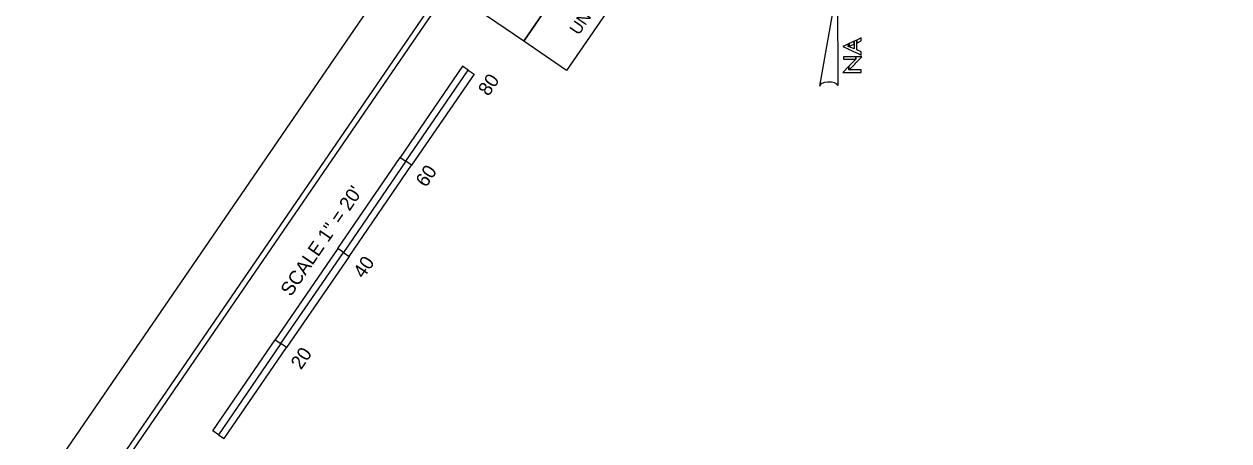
# Model space of a CAD drawing. Extents: x 1439200 to 1642184, y 394112 to 606444.
# Drawn here: x 1641658.3 to 1641876.4, y 394691.9 to 394767.3 of the extents above; entities that cross this region are included whole.
import ezdxf

# ---------------------------------------------------------------- set-up
doc = ezdxf.new("R2010")
doc.units = 0
for name, color, linetype in [('North Arrow NAD83 CELL', 7, 'Continuous'), ('Old_Level_20', 7, 'Continuous'), ('Old_Level_60', 7, 'Continuous'), ('Sheet Plot Border Inside CELL', 7, 'Continuous'), ('Sheet Plot Border Outside CELL', 7, 'Continuous'), ('Sheet Sticker Exception Certification CELL', 7, 'Continuous'), ('UC Plan Sheet 34 CELL', 7, 'Continuous')]:
    doc.layers.add(name, color=color, linetype=linetype)

msp = doc.modelspace()

# ---------------------------------------------------------------- linework, layer by layer
at = {"layer": 'North Arrow NAD83 CELL'}
for p, q in [((1641805.65, 394775), (1641802.31, 394756.1)), ((1641805.67, 394756.18), (1641805.65, 394775))]:
    msp.add_line(p, q, dxfattribs=at)
for points in [[(1641809.04, 394762.09), (1641809.86, 394761.71), (1641809.86, 394762.26), (1641809.04, 394762.62), (1641809.04, 394764.41), (1641808.61, 394764.21), (1641808.61, 394762.82), (1641807.89, 394763.14), (1641807.88, 394763.14), (1641807.7, 394763.21), (1641807.7, 394763.21), (1641807.52, 394763.26), (1641807.52, 394763.7), (1641806.56, 394763.25), (1641807.52, 394762.8), (1641807.7, 394762.72), (1641807.7, 394762.72), (1641807.88, 394762.63), (1641807.89, 394762.63), (1641808.61, 394762.29)], [(1641807.52, 394763.26), (1641807.7, 394763.31), (1641807.7, 394763.78), (1641807.52, 394763.7)], [(1641807.89, 394763.38), (1641808.61, 394763.7), (1641808.61, 394764.21), (1641807.89, 394763.87), (1641807.88, 394763.87), (1641807.7, 394763.79), (1641807.7, 394763.78), (1641807.7, 394763.31), (1641807.7, 394763.31), (1641807.88, 394763.38)], [(1641809.04, 394763.88), (1641809.86, 394764.25), (1641809.86, 394764.79), (1641809.04, 394764.41)], [(1641808.89, 394758.57), (1641809.87, 394758.57), (1641809.87, 394759.04), (1641808.89, 394759.04), (1641808.68, 394759.04), (1641808.5, 394759.04), (1641808.01, 394759.04), (1641807.82, 394759.04), (1641807.65, 394759.04), (1641807.65, 394759.71), (1641806.56, 394758.57), (1641807.65, 394758.57), (1641807.82, 394758.57), (1641808.01, 394758.57), (1641808.5, 394758.57), (1641808.68, 394758.57)], [(1641808.68, 394760.94), (1641808.89, 394760.94), (1641808.89, 394761.41), (1641808.68, 394761.41), (1641808.5, 394761.41), (1641808.01, 394761.41), (1641807.82, 394761.41), (1641806.68, 394761.41), (1641806.68, 394760.94), (1641807.82, 394760.94), (1641808.01, 394760.94), (1641808.5, 394760.94)], [(1641809.86, 394761.29), (1641809.99, 394761.41), (1641809.86, 394761.41), (1641808.89, 394761.41), (1641808.89, 394760.94), (1641808.68, 394760.76), (1641808.5, 394760.59), (1641808.01, 394760.07), (1641807.82, 394759.88), (1641807.65, 394759.71), (1641807.65, 394759.04), (1641807.82, 394759.17), (1641808.01, 394759.35), (1641808.5, 394759.87), (1641808.68, 394760.05), (1641808.89, 394760.27)]]:
    msp.add_lwpolyline(points, close=True, dxfattribs=at)
msp.add_ellipse((1641804, 394756.03), major_axis=(1.69, -0.01), ratio=0.461098, start_param=0.201328, end_param=3.141593, dxfattribs=at)
at = {"layer": 'Old_Level_20'}
for points in [[(1641727.43, 394742.48), (1641738.74, 394758.97), (1641737.71, 394759.68), (1641726.4, 394743.18), (1641727.43, 394742.48)], [(1641717.15, 394725.27), (1641728.46, 394741.77), (1641727.43, 394742.48), (1641716.12, 394725.98), (1641717.15, 394725.27)], [(1641704.81, 394709.49), (1641716.12, 394725.98), (1641715.09, 394726.69), (1641703.78, 394710.19), (1641704.81, 394709.49)], [(1641694.53, 394692.29), (1641705.84, 394708.78), (1641704.81, 394709.49), (1641693.5, 394692.99), (1641694.53, 394692.29)]]:
    msp.add_lwpolyline(points, dxfattribs=at)
for points in [[(1641727.43, 394742.48), (1641738.74, 394758.97), (1641739.78, 394758.26), (1641728.46, 394741.77)], [(1641715.09, 394726.69), (1641726.4, 394743.18), (1641727.43, 394742.48), (1641716.12, 394725.98)], [(1641704.81, 394709.49), (1641716.12, 394725.98), (1641717.15, 394725.27), (1641705.84, 394708.78)], [(1641692.47, 394693.7), (1641703.78, 394710.19), (1641704.81, 394709.49), (1641693.5, 394692.99)]]:
    msp.add_lwpolyline(points, close=True, dxfattribs=at)
at = {"layer": 'Old_Level_60'}
msp.add_lwpolyline([(1641735.12, 394773.58), (1641780.37, 394839.57), (1641794.03, 394830.21), (1641748.77, 394764.22)], close=True, dxfattribs=at)
at = {"layer": 'Sheet Plot Border Inside CELL'}
msp.add_lwpolyline([(1641827.57, 394910.19), (1641450.57, 394360.44), (1641798.64, 394121.75), (1642175.63, 394671.51)], close=True, dxfattribs=at)
at = {"layer": 'Sheet Plot Border Outside CELL'}
msp.add_lwpolyline([(1641821.18, 394916.76), (1641440.23, 394361.23), (1641803.1, 394112.39), (1642184.06, 394667.92)], close=True, dxfattribs=at)
at = {"layer": 'Sheet Sticker Exception Certification CELL'}
for p, q in [((1641748.77, 394764.22), (1641794.03, 394830.21)), ((1641801.78, 394824.89), (1641756.53, 394758.9)), ((1641756.53, 394758.9), (1641748.77, 394764.22))]:
    msp.add_line(p, q, dxfattribs=at)
at = {"layer": 'UC Plan Sheet 34 CELL'}
msp.add_lwpolyline([(1641825.58, 394905.49), (1641486.25, 394410.66), (1641832.63, 394173.13), (1642171.96, 394667.96)], close=True, dxfattribs=at)

# ---------------------------------------------------------------- texts
at = {"layer": 'Old_Level_20'}
for s, p in [('80', (1641742.39, 394754.12)), ('60', (1641731.08, 394737.62)), ('SCALE 1" = 20\'', (1641706.62, 394717.87)), ('40', (1641719.77, 394721.13)), ('20', (1641708.46, 394704.63))]:
    msp.add_text(s, height=2.5, rotation=55.5597, dxfattribs=at).set_placement(p)
at = {"layer": 'Sheet Sticker Exception Certification CELL'}
msp.add_text('UNLESS ALL SIGNATURES COMPLETED', height=2.2, rotation=55.5597, dxfattribs=at).set_placement((1641758.71, 394765.16))

doc.saveas('drawing.dxf')
